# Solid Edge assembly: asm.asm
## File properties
Author: Deepak Maini
Template: Normal.asm
Last saved by: MYPC
Revision: 6
Application: Solid Edge
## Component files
multi-1-plate.par
multi-2-plate.par
multi-3.par
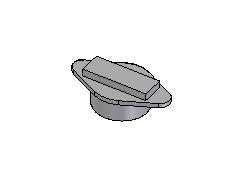
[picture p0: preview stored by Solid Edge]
